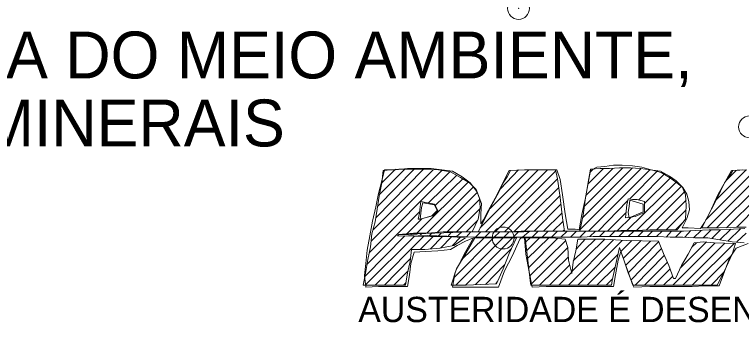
# Model space of a CAD drawing. Extents: x 0 to 1682, y 0 to 1188.
# Drawn here: x 1345.26 to 1366.85, y 45.57 to 54.72 of the extents above; entities that cross this region are included whole.
import ezdxf

# ---------------------------------------------------------------- set-up
doc = ezdxf.new("R2010")
doc.units = 0
doc.header["$LTSCALE"] = 1.3
doc.header["$PDMODE"] = 32
doc.header["$PDSIZE"] = 0.65
for name, color, linetype, lineweight in [('12', 7, 'Continuous', 13), ('50', 7, 'Continuous', 13), ('51', 7, 'Continuous', 13), ('52', 7, 'Continuous', 13)]:
    doc.layers.add(name, color=color, linetype=linetype, lineweight=lineweight)
doc.layers.add('53', color=7, linetype='Continuous')

msp = doc.modelspace()

# ---------------------------------------------------------------- linework, layer by layer
at = {"layer": '12'}
for points in [[(1363.652, 46.621), (1363.612, 46.701), (1363.512, 46.981), (1363.272, 47.681), (1363.192, 47.421), (1363.112, 46.981), (1363.052, 46.641), (1362.652, 46.641), (1362.232, 46.641), (1361.812, 46.641), (1361.432, 46.641), (1361.052, 46.641), (1360.632, 46.621), (1360.532, 47.121), (1360.452, 47.601), (1360.412, 48.081), (1360.372, 48.081), (1360.312, 48.081), (1360.272, 48.041), (1360.052, 47.561), (1359.812, 47.101), (1359.632, 46.621), (1359.172, 46.621), (1358.732, 46.621), (1358.272, 46.621), (1358.352, 47.061), (1358.612, 47.601), (1358.892, 48.081), (1358.652, 47.981), (1358.412, 47.861), (1358.212, 47.741), (1357.832, 47.701), (1357.472, 47.681), (1357.132, 47.661), (1357.032, 47.321), (1356.992, 46.981), (1356.932, 46.641), (1356.492, 46.641), (1356.072, 46.641), (1355.692, 46.621), (1355.652, 46.961), (1355.692, 47.321), (1355.732, 47.721), (1355.812, 48.141), (1355.892, 48.581), (1355.992, 49.001), (1356.072, 49.401), (1356.172, 49.781), (1356.252, 50.101), (1356.572, 50.101), (1356.932, 50.141), (1357.292, 50.141), (1357.632, 50.141), (1357.952, 50.101), (1358.272, 50.061), (1358.552, 49.901), (1358.792, 49.721), (1358.992, 49.461), (1359.132, 49.101), (1359.112, 48.801), (1359.112, 48.621), (1359.112, 48.501), (1359.192, 48.621), (1359.292, 48.821), (1359.532, 49.261), (1359.952, 50.081), (1360.412, 50.101), (1360.892, 50.101), (1361.372, 50.101), (1361.472, 49.821), (1361.532, 49.361), (1361.612, 48.801), (1361.692, 48.341), (1361.812, 48.341), (1361.912, 48.341), (1362.032, 48.321), (1362.112, 48.781), (1362.212, 49.221), (1362.292, 49.661), (1362.372, 50.081), (1362.552, 50.181), (1362.792, 50.201), (1363.052, 50.241), (1363.312, 50.241), (1363.612, 50.221), (1363.892, 50.181), (1364.172, 50.101), (1364.472, 50.021), (1364.712, 49.881), (1364.932, 49.721), (1365.112, 49.581), (1365.232, 49.381), (1365.292, 49.161), (1365.312, 48.921), (1365.232, 48.661), (1365.092, 48.381), (1365.272, 48.381)], [(1365.272, 48.381), (1365.632, 48.361), (1365.752, 48.541), (1365.912, 48.841), (1366.152, 49.361), (1366.552, 50.081), (1366.892, 50.101)], [(1367.052, 47.921), (1366.692, 47.781), (1366.492, 47.481), (1366.352, 47.081), (1366.192, 46.661), (1365.772, 46.661), (1365.392, 46.641), (1364.952, 46.641), (1364.532, 46.641), (1364.132, 46.641), (1363.652, 46.621)]]:
    msp.add_lwpolyline(points, dxfattribs=at)
for points in [[(1357.312, 48.641), (1357.332, 48.821), (1357.352, 48.981), (1357.392, 49.121), (1357.732, 49.061), (1357.812, 48.901), (1357.652, 48.741)], [(1363.512, 48.681), (1363.492, 48.841), (1363.512, 49.021), (1363.532, 49.201), (1363.932, 49.081), (1363.932, 48.861)]]:
    msp.add_lwpolyline(points, close=True, dxfattribs=at)
at = {"layer": '50'}
for p, q in [((1355.912, 48.321), (1357.692, 50.101)), ((1355.992, 48.681), (1357.412, 50.121)), ((1356.052, 49.021), (1357.132, 50.121)), ((1356.092, 49.361), (1356.852, 50.121)), ((1356.172, 49.721), (1356.572, 50.121)), ((1359.092, 48.381), (1360.812, 50.101)), ((1359.252, 48.261), (1361.092, 50.101)), ((1359.392, 48.961), (1360.532, 50.101)), ((1359.692, 49.541), (1360.232, 50.101)), ((1362.052, 48.321), (1363.872, 50.141)), ((1362.132, 48.681), (1363.612, 50.161)), ((1362.192, 49.021), (1363.332, 50.161)), ((1362.232, 49.341), (1363.032, 50.141)), ((1362.292, 49.681), (1362.752, 50.141)), ((1362.312, 48.281), (1364.132, 50.101)), ((1362.352, 50.021), (1362.452, 50.121)), ((1365.792, 48.621), (1367.272, 50.101)), ((1365.832, 48.381), (1367.552, 50.101)), ((1366.112, 49.221), (1366.992, 50.101)), ((1366.112, 48.381), (1367.832, 50.101)), ((1355.792, 47.641), (1358.192, 50.041)), ((1355.852, 47.981), (1357.952, 50.081)), ((1356.212, 50.041), (1356.252, 50.081)), ((1357.552, 49.121), (1358.392, 49.941)), ((1359.532, 48.261), (1361.332, 50.061)), ((1363.532, 49.241), (1364.372, 50.081)), ((1363.792, 49.201), (1364.572, 50.001)), ((1363.972, 49.101), (1364.752, 49.881)), ((1366.412, 49.801), (1366.692, 50.081)), ((1366.412, 48.381), (1367.952, 49.921)), ((1357.212, 48.221), (1358.732, 49.741)), ((1357.752, 49.041), (1358.572, 49.841)), ((1359.812, 48.261), (1361.392, 49.841)), ((1363.452, 48.301), (1364.932, 49.761)), ((1366.712, 48.401), (1368.012, 49.721)), ((1357.512, 48.221), (1358.892, 49.601)), ((1360.112, 48.281), (1361.432, 49.581)), ((1363.732, 48.301), (1365.072, 49.621)), ((1357.812, 48.241), (1359.012, 49.441)), ((1360.412, 48.281), (1361.472, 49.341)), ((1364.032, 48.321), (1365.152, 49.441)), ((1358.112, 48.261), (1359.072, 49.221)), ((1360.692, 48.281), (1361.492, 49.081)), ((1362.592, 48.281), (1363.472, 49.181)), ((1364.332, 48.321), (1365.212, 49.201)), ((1355.732, 47.301), (1357.292, 48.861)), ((1358.392, 48.261), (1359.092, 48.961)), ((1360.972, 48.281), (1361.512, 48.821)), ((1362.872, 48.281), (1363.432, 48.841)), ((1364.612, 48.321), (1365.212, 48.921)), ((1356.912, 48.201), (1357.372, 48.661)), ((1358.672, 48.261), (1359.012, 48.601)), ((1361.252, 48.281), (1361.552, 48.581)), ((1363.172, 48.301), (1363.572, 48.701)), ((1364.892, 48.321), (1365.132, 48.561)), ((1361.532, 48.281), (1361.592, 48.321)), ((1355.672, 46.941), (1356.852, 48.141)), ((1355.672, 46.681), (1357.132, 48.121)), ((1355.972, 46.681), (1357.412, 48.121)), ((1357.312, 47.741), (1357.692, 48.121)), ((1357.612, 47.761), (1357.972, 48.121)), ((1357.912, 47.781), (1358.252, 48.121)), ((1358.272, 47.861), (1358.512, 48.101)), ((1358.312, 46.901), (1359.492, 48.081)), ((1358.372, 46.681), (1359.772, 48.081)), ((1358.532, 47.421), (1359.212, 48.081)), ((1358.652, 46.681), (1360.052, 48.081)), ((1360.452, 47.961), (1360.572, 48.081)), ((1360.472, 47.701), (1360.852, 48.081)), ((1360.492, 47.461), (1361.132, 48.081)), ((1360.532, 47.201), (1361.392, 48.061)), ((1360.552, 46.941), (1361.632, 48.001)), ((1361.712, 46.681), (1363.052, 48.021)), ((1361.812, 47.081), (1362.792, 48.041)), ((1361.852, 47.401), (1362.512, 48.041)), ((1361.952, 47.761), (1362.212, 48.041)), ((1361.992, 46.681), (1363.312, 48.001)), ((1363.272, 47.681), (1363.592, 48.001)), ((1363.352, 47.481), (1363.872, 48.001)), ((1363.412, 47.261), (1364.152, 47.981)), ((1363.492, 47.041), (1364.392, 47.961)), ((1364.812, 46.681), (1366.072, 47.941)), ((1365.032, 47.181), (1365.812, 47.961)), ((1365.372, 47.801), (1365.512, 47.941)), ((1358.952, 46.701), (1360.012, 47.761)), ((1360.592, 46.701), (1361.692, 47.801)), ((1363.572, 46.841), (1364.472, 47.761)), ((1365.112, 46.681), (1366.352, 47.921)), ((1365.392, 46.681), (1366.632, 47.921)), ((1360.852, 46.681), (1361.712, 47.521)), ((1362.272, 46.681), (1363.192, 47.601)), ((1363.692, 46.681), (1364.552, 47.561)), ((1365.672, 46.681), (1366.552, 47.561)), ((1356.252, 46.681), (1357.012, 47.461)), ((1363.972, 46.681), (1364.652, 47.361)), ((1356.532, 46.681), (1356.952, 47.101)), ((1359.252, 46.701), (1359.812, 47.281)), ((1361.152, 46.681), (1361.752, 47.281)), ((1362.552, 46.681), (1363.112, 47.221)), ((1364.252, 46.681), (1364.732, 47.161)), ((1361.432, 46.681), (1361.812, 47.061)), ((1362.832, 46.681), (1363.012, 46.861)), ((1364.532, 46.681), (1364.812, 46.941)), ((1365.952, 46.681), (1366.332, 47.061)), ((1356.812, 46.681), (1356.892, 46.761)), ((1359.552, 46.721), (1359.592, 46.781))]:
    msp.add_line(p, q, dxfattribs=at)
for points in [[(1355.612, 46.681), (1355.692, 47.081), (1355.752, 47.441), (1355.832, 47.821), (1355.872, 48.201), (1355.972, 48.561), (1356.032, 48.941), (1356.092, 49.321), (1356.172, 49.721), (1356.212, 50.081), (1356.672, 50.121), (1357.312, 50.121), (1357.852, 50.101), (1358.212, 50.041), (1358.512, 49.881), (1358.772, 49.721), (1358.972, 49.521), (1359.072, 49.261), (1359.092, 48.981), (1359.032, 48.641), (1358.852, 48.261), (1358.412, 48.261), (1357.992, 48.261), (1357.532, 48.221), (1357.112, 48.221), (1356.672, 48.181), (1356.672, 48.181), (1356.652, 48.161), (1356.632, 48.141), (1357.612, 48.121), (1358.132, 48.121), (1358.412, 48.101), (1358.652, 48.081), (1358.312, 47.861), (1357.892, 47.781), (1357.452, 47.741), (1357.052, 47.741), (1357.012, 47.381), (1356.932, 47.041), (1356.872, 46.681), (1356.452, 46.681), (1356.052, 46.681)], [(1359.032, 48.261), (1359.412, 49.001), (1359.652, 49.461), (1359.772, 49.721), (1359.892, 49.901), (1359.992, 50.081), (1360.412, 50.101), (1360.892, 50.101), (1361.332, 50.101), (1361.392, 49.841), (1361.472, 49.281), (1361.532, 48.681), (1361.592, 48.281), (1361.152, 48.281), (1360.732, 48.281), (1360.312, 48.281), (1359.872, 48.261), (1359.452, 48.261)], [(1362.052, 48.281), (1362.152, 48.761), (1362.212, 49.201), (1362.292, 49.681), (1362.372, 50.121), (1362.652, 50.141), (1362.932, 50.141), (1363.232, 50.161), (1363.552, 50.161), (1363.852, 50.141), (1364.152, 50.101), (1364.452, 50.061), (1364.712, 49.921), (1364.912, 49.781), (1365.092, 49.601), (1365.192, 49.361), (1365.212, 49.041), (1365.192, 48.641), (1365.192, 48.641), (1365.032, 48.441), (1364.972, 48.361), (1364.952, 48.321), (1364.512, 48.321), (1364.132, 48.321), (1363.692, 48.301), (1363.272, 48.301), (1362.872, 48.281), (1362.472, 48.281)], [(1363.412, 48.681), (1363.432, 48.881), (1363.452, 49.061), (1363.492, 49.241), (1363.612, 49.221), (1363.752, 49.221), (1363.972, 49.161), (1363.972, 48.841), (1363.692, 48.721)], [(1357.312, 48.641), (1357.292, 48.641), (1357.292, 48.641), (1357.252, 48.641), (1357.292, 48.821), (1357.312, 49.001), (1357.332, 49.161), (1357.732, 49.081), (1357.832, 48.901), (1357.672, 48.741)], [(1358.232, 46.681), (1358.392, 47.161), (1358.672, 47.641), (1358.932, 48.081), (1359.352, 48.081), (1359.772, 48.081), (1360.172, 48.081), (1359.952, 47.621), (1359.772, 47.161), (1359.572, 46.721), (1359.112, 46.701), (1358.672, 46.681)], [(1360.592, 46.681), (1360.572, 46.821), (1360.532, 47.161), (1360.432, 48.081), (1360.832, 48.081), (1361.232, 48.081), (1361.612, 48.041), (1361.692, 47.801), (1361.712, 47.421), (1361.812, 47.021), (1361.852, 47.361), (1361.932, 47.701), (1361.992, 48.041), (1362.052, 48.041), (1362.172, 48.041), (1362.392, 48.041), (1362.792, 48.041), (1363.432, 48.001), (1364.392, 47.981), (1364.532, 47.621), (1364.692, 47.261), (1364.832, 46.881), (1364.852, 46.881), (1364.852, 46.881), (1364.892, 46.881), (1365.072, 47.261), (1365.272, 47.601), (1365.452, 47.941), (1365.712, 47.961), (1366.032, 47.941), (1366.672, 47.921), (1366.572, 47.601), (1366.352, 47.101), (1366.132, 46.681), (1365.712, 46.681), (1365.292, 46.681), (1364.872, 46.681), (1364.452, 46.681), (1364.032, 46.681), (1363.632, 46.681), (1363.492, 47.041), (1363.332, 47.521), (1363.232, 47.801), (1363.072, 47.081), (1363.012, 46.821), (1362.992, 46.681), (1362.572, 46.681), (1362.212, 46.681), (1361.812, 46.681), (1361.392, 46.681), (1361.012, 46.681)]]:
    msp.add_lwpolyline(points, close=True, dxfattribs=at)
msp.add_lwpolyline([(1366.992, 48.401), (1366.692, 48.401), (1366.192, 48.381), (1365.672, 48.381), (1366.112, 49.221), (1366.352, 49.721), (1366.492, 49.921), (1366.592, 50.081), (1367.012, 50.101)], dxfattribs=at)
msp.add_point((1359.772, 48.081), dxfattribs=at)
at = {"layer": '51'}
for p, q in [((1356.752, 48.181), (1356.772, 48.181)), ((1357.032, 48.161), (1357.052, 48.201)), ((1357.312, 48.161), (1357.352, 48.201)), ((1357.572, 48.141), (1357.652, 48.221)), ((1357.852, 48.141), (1357.932, 48.221)), ((1358.132, 48.121), (1358.232, 48.241)), ((1358.392, 48.121), (1358.532, 48.241)), ((1358.672, 48.101), (1358.812, 48.261)), ((1358.952, 48.101), (1359.112, 48.261)), ((1359.232, 48.101), (1359.392, 48.261)), ((1359.512, 48.101), (1359.672, 48.261)), ((1359.792, 48.101), (1359.952, 48.261)), ((1360.072, 48.101), (1360.232, 48.261)), ((1360.352, 48.101), (1360.532, 48.261)), ((1360.632, 48.101), (1360.812, 48.281)), ((1360.932, 48.101), (1361.112, 48.281)), ((1361.212, 48.101), (1361.392, 48.281)), ((1361.492, 48.101), (1361.672, 48.281)), ((1361.772, 48.101), (1361.952, 48.281)), ((1362.052, 48.101), (1362.232, 48.281)), ((1362.352, 48.121), (1362.512, 48.281)), ((1362.632, 48.121), (1362.792, 48.281)), ((1362.932, 48.121), (1363.092, 48.281)), ((1363.212, 48.121), (1363.372, 48.281)), ((1363.492, 48.121), (1363.652, 48.281)), ((1363.772, 48.121), (1363.932, 48.281)), ((1364.052, 48.121), (1364.212, 48.281)), ((1364.332, 48.121), (1364.492, 48.281)), ((1364.612, 48.101), (1364.772, 48.281)), ((1364.892, 48.101), (1365.072, 48.281)), ((1365.172, 48.101), (1365.352, 48.301)), ((1365.432, 48.081), (1365.652, 48.301)), ((1365.712, 48.081), (1365.952, 48.321)), ((1365.972, 48.061), (1366.232, 48.321)), ((1366.212, 48.021), (1366.532, 48.341)), ((1366.452, 47.981), (1366.832, 48.361)), ((1366.712, 47.961), (1366.992, 48.221))]:
    msp.add_line(p, q, dxfattribs=at)
msp.add_lwpolyline([(1366.932, 47.941), (1366.572, 47.961), (1366.212, 48.021), (1365.852, 48.081), (1365.472, 48.081), (1365.112, 48.101), (1364.732, 48.101), (1364.352, 48.121), (1363.972, 48.121), (1363.592, 48.121), (1363.212, 48.121), (1362.852, 48.121), (1362.452, 48.121), (1362.092, 48.101), (1361.712, 48.101), (1361.332, 48.101), (1360.972, 48.101), (1360.612, 48.101), (1360.272, 48.101), (1359.832, 48.101), (1359.392, 48.101), (1358.952, 48.101), (1356.672, 48.181), (1358.812, 48.261), (1359.032, 48.261), (1359.652, 48.261), (1360.052, 48.261), (1360.392, 48.261), (1360.752, 48.281), (1361.112, 48.281), (1361.472, 48.281), (1361.852, 48.281), (1362.212, 48.281), (1362.572, 48.281), (1362.932, 48.281), (1363.312, 48.281), (1363.672, 48.281), (1364.032, 48.281), (1364.412, 48.281), (1364.772, 48.281), (1365.132, 48.281), (1365.492, 48.301), (1365.892, 48.321), (1366.232, 48.321), (1366.612, 48.341), (1366.952, 48.361)], dxfattribs=at)
msp.add_point((1367.092, 51.381), dxfattribs=at)
at = {"layer": '52'}
msp.add_point((1360.232, 54.901), dxfattribs=at)

# ---------------------------------------------------------------- texts
at = {"layer": '53'}
for s, height, p in [('SECRETARIA EXTRAORDINÁRIA DO MEIO AMBIENTE,', 1.393, (1317.272, 52.821)), ('DOS RECURSOS HÍDRICOS E MINERAIS', 1.393, (1317.272, 50.801)), ('AUSTERIDADE É DESENVOLVIMENTO', 0.751, (1355.472, 45.581))]:
    msp.add_text(s, height=height, dxfattribs=at).set_placement(p)

doc.saveas('drawing.dxf')
